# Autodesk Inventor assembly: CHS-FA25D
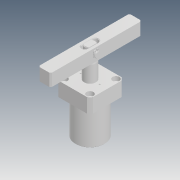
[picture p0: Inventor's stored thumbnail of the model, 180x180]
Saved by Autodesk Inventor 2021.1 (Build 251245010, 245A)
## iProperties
Created: 2019-05
Part Number: CHS-FA25D
Description: STEP AP214
Document SubType Name: Assembly
Designer: user
Title: chs-fa25d_asm.STEP
Revision Number: ÈÎºÎ
Sending System: SolidWorks 2016
Preprocessor: SwSTEP 2.0
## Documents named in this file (6)
- D:\Vault_2016\Projekty\Clamptek\Hydraulic\CHS\CHS-25\Inventor\CHS-FA25D\CHS-FA25D.iam
- D:\Vault_2016\Projekty\Clamptek\Hydraulic\CHS\CHS-25\Inventor\CHS-FA25D\CHS-25D-02_1.ipt
- D:\Vault_2016\Projekty\Clamptek\Hydraulic\CHS\CHS-25\Inventor\CHS-FA25D\CHS-25D-01_1.ipt
- D:\Vault_2016\Projekty\Clamptek\Hydraulic\CHS\CHS-25\Inventor\CHS-FA25D\Öá8µ²È¦.ipt
- D:\Vault_2016\Projekty\Clamptek\Hydraulic\CHS\CHS-25\Inventor\CHS-FA25D\Xiao.ipt
- D:\Vault_2016\Projekty\Clamptek\Hydraulic\CHS\CHS-25\Inventor\CHS-FA25D\CHS-FA25BT.ipt
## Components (6 placed, 6 different names)
1. CHS-25D-02_1_1
2. CHS-25D-01_1_2
3. Öá8µ²È¦_3
4. Xiao_4
5. Öá8µ²È¦_5
6. CHS-FA25BT_6
